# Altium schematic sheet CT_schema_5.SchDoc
size 284 x 243 mm
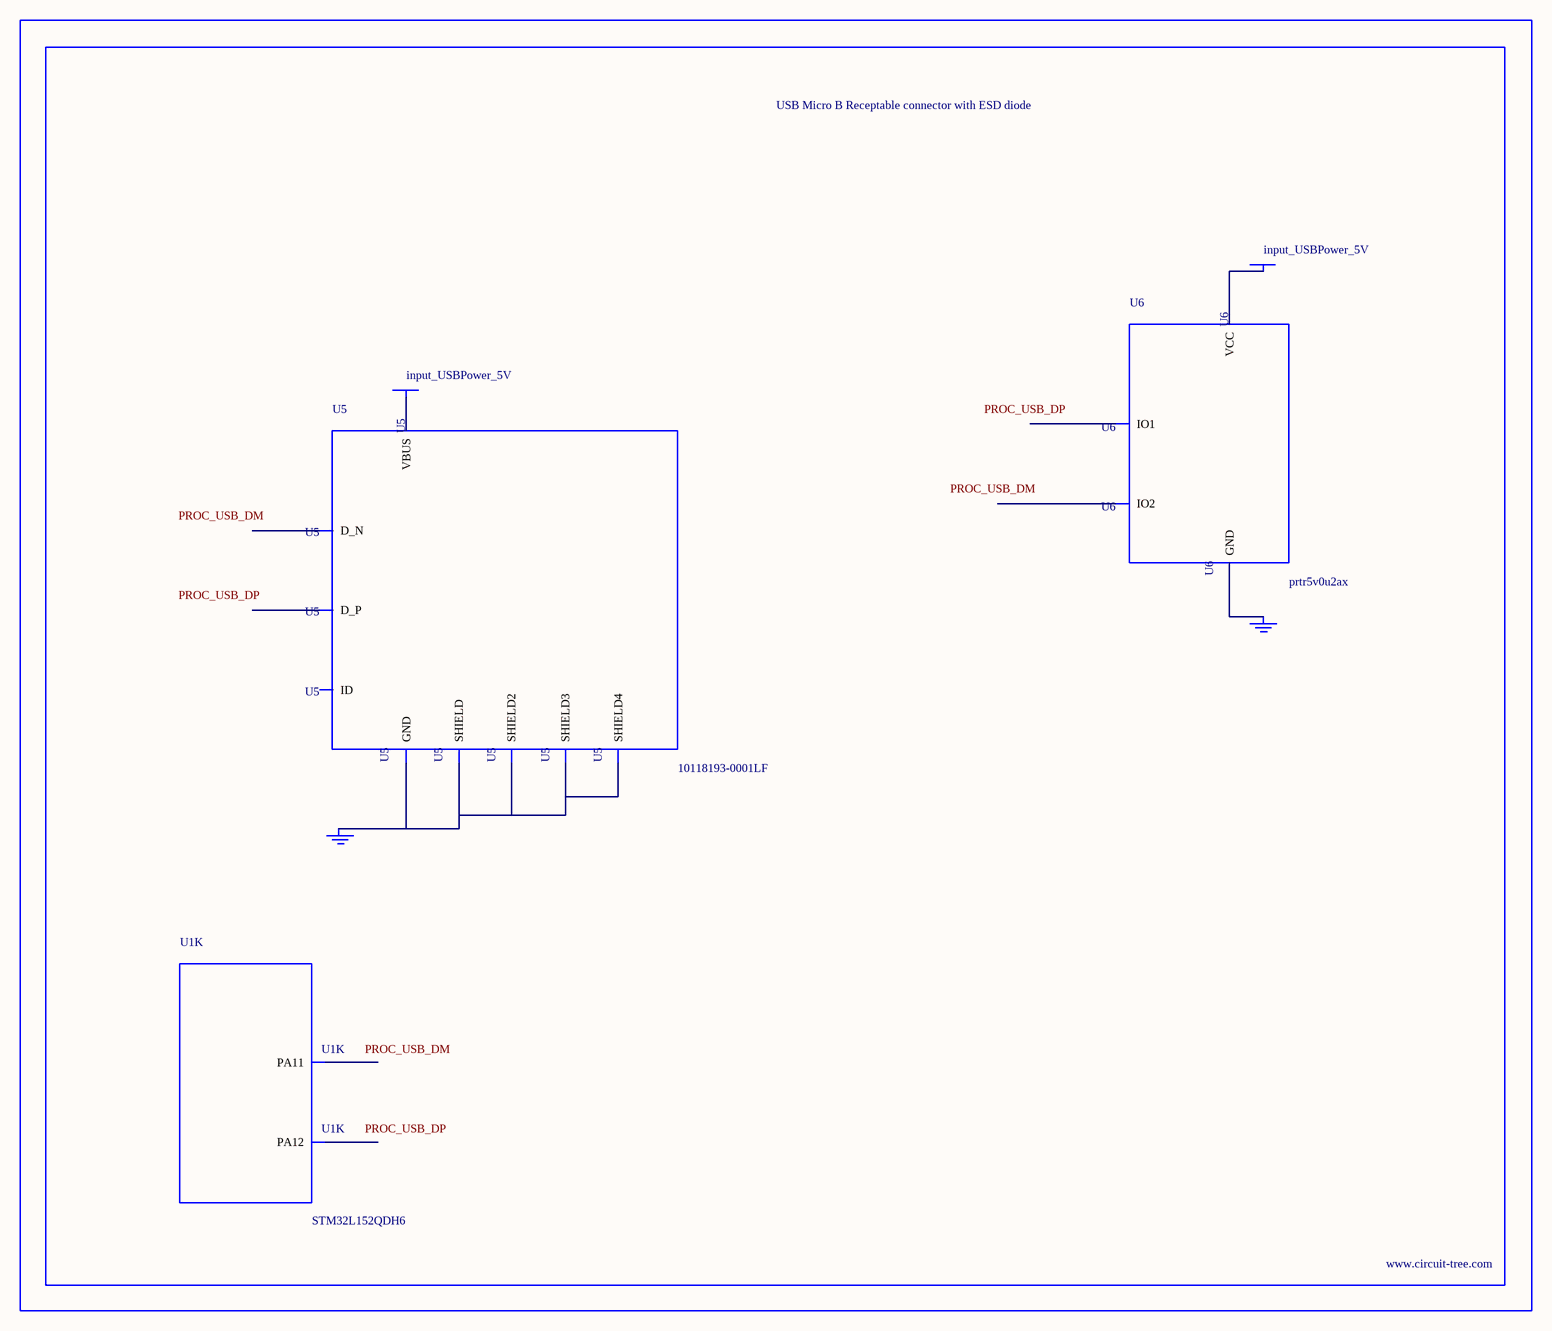
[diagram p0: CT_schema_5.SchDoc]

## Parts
BORDER4  (no value)
GND_INSTANCE_4_0  (no value)
GND_INSTANCE_4_1  (no value)
POWER_INSTANCE_4_0  input_USBPower_5V
POWER_INSTANCE_4_1  input_USBPower_5V
U1  STM32L152QDH6  [UFBGA132]  (part K of 11)
U5  10118193-0001LF  [FCI_10118193-0001LF]
U6  prtr5v0u2ax  [SOT143B]

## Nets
NetGND_INSTANCE_4_0_0: GND_INSTANCE_4_0.0(GND) U5.5(GND) U5.6(SHIELD) U5.7(SHIELD2) U5.8(SHIELD3) U5.9(SHIELD4)
NetGND_INSTANCE_4_1_0: GND_INSTANCE_4_1.0(GND) U6.1(GND)
NetPOWER_INSTANCE_4_0_0: POWER_INSTANCE_4_0.0(PWR) U5.1(VBUS)
NetPOWER_INSTANCE_4_1_0: POWER_INSTANCE_4_1.0(PWR) U6.4(VCC)

Not connected (* = marked no-connect by the designer): U1 A12(PA12) B12(PA11); U5 2(D_N) 3(D_P) 4(ID); U6 2(IO1) 3(IO2)

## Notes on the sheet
- Labels drawn without touching a wire or pin: PROC_USB_DM, PROC_USB_DP

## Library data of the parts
BORDER4 = BORDER_PAGE4
GND_INSTANCE_4_0 GND_INSTANCE_4_1 = GND
POWER_INSTANCE_4_0 POWER_INSTANCE_4_1 = PWR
